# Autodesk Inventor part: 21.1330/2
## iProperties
Created: 2006-12
Part Number: 21.1330/2
Document SubType Name: Modeling
Designer: Andy Moles
Material: Steel, Mild
Density: 7.86 g/cm^3
Description: M6 SQUARE NUT POS FXG
Mass: 5.20492 g
Surface Area: 8.43697 cm^2
Volume: 0.662203 cm^3
Vendor: S
Author: Andy Moles
Title: M6 SQUARE NUT POS FXG
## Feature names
1. Extrusion1
2. Revolution1
3. Fillet2
4. Extrusion3
